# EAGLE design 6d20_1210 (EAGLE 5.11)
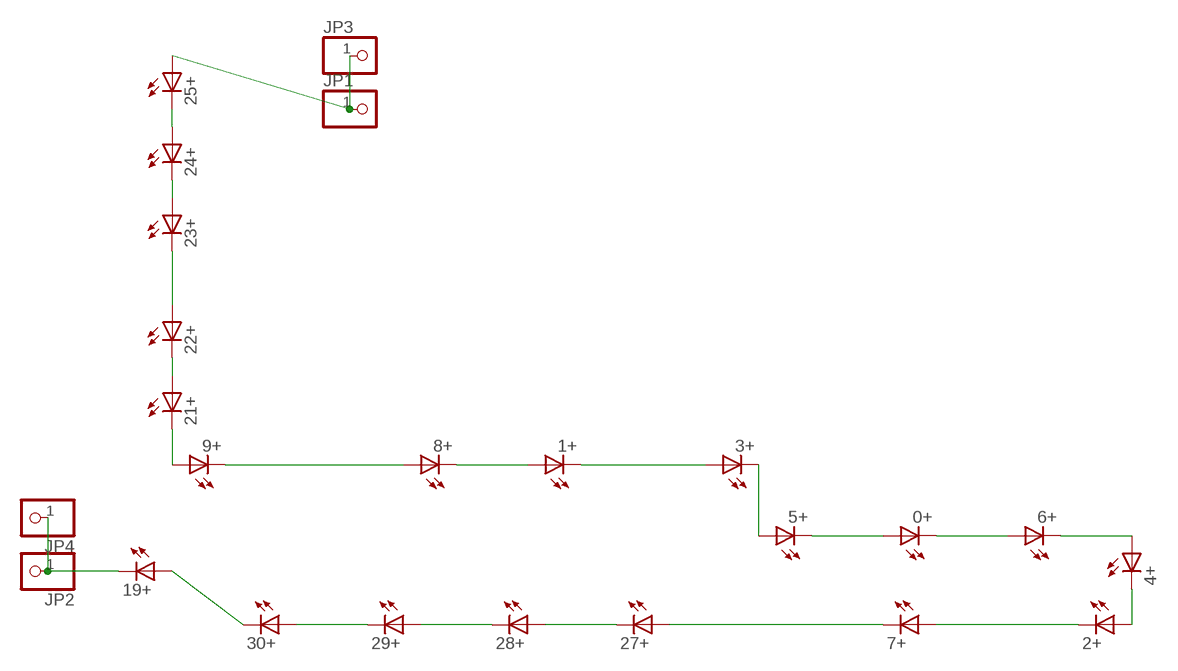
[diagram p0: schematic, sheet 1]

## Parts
0+  LED1210  [1210]
1+  LED1210  [1210]
2+  LED1210  [1210]
3+  LED1210  [1210]
4+  LED1210  [1210]
5+  LED1210  [1210]
6+  LED1210  [1210]
7+  LED1210  [1210]
8+  LED1210  [1210]
9+  LED1210  [1210]
19+  LED1210  [1210]
21+  LED1210  [1210]
22+  LED1210  [1210]
23+  LED1210  [1210]
24+  LED1210  [1210]
25+  LED1210  [1210]
27+  LED1210  [1210]
28+  LED1210  [1210]
29+  LED1210  [1210]
30+  LED1210  [1210]
JP1  PINHD-1X11MM6  [1X1MM8]
JP2  PINHD-1X11MM6  [1X1MM8]
JP3  PINHD-1X11X0.4  [1X01]
JP4  PINHD-1X11X0.4  [1X01]

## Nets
MINUS: 19+.P$2(C) JP2.1 JP4.1
N$4: 19+.P$1(A) 30+.P$2(C)
N$6: 8+.P$1(A) 9+.P$2(C)
N$7: 29+.P$2(C) 30+.P$1(A)
N$8: 28+.P$2(C) 29+.P$1(A)
N$9: 27+.P$2(C) 28+.P$1(A)
N$12: 2+.P$2(C) 7+.P$1(A)
N$13: 7+.P$2(C) 27+.P$1(A)
N$14: 2+.P$1(A) 4+.P$2(C)
N$15: 4+.P$1(A) 6+.P$2(C)
N$16: 0+.P$2(C) 6+.P$1(A)
N$17: 0+.P$1(A) 5+.P$2(C)
N$18: 3+.P$2(C) 5+.P$1(A)
N$19: 1+.P$2(C) 3+.P$1(A)
N$20: 1+.P$1(A) 8+.P$2(C)
N$23: 9+.P$1(A) 21+.P$2(C)
N$24: 21+.P$1(A) 22+.P$2(C)
N$25: 22+.P$1(A) 23+.P$2(C)
N$26: 24+.P$1(A) 25+.P$2(C)
N$28: 23+.P$1(A) 24+.P$2(C)
PLUS: 25+.P$1(A) JP1.1 JP3.1

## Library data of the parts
0+ 1+ 2+ 3+ 4+ 5+ 6+ 7+ 8+ 9+ 19+ 21+ 22+ 23+ 24+ 25+ 27+ 28+ 29+ 30+ = led(2):LED: LED
JP1-JP4 = pinhead:PINHD-1X1: PIN HEADER

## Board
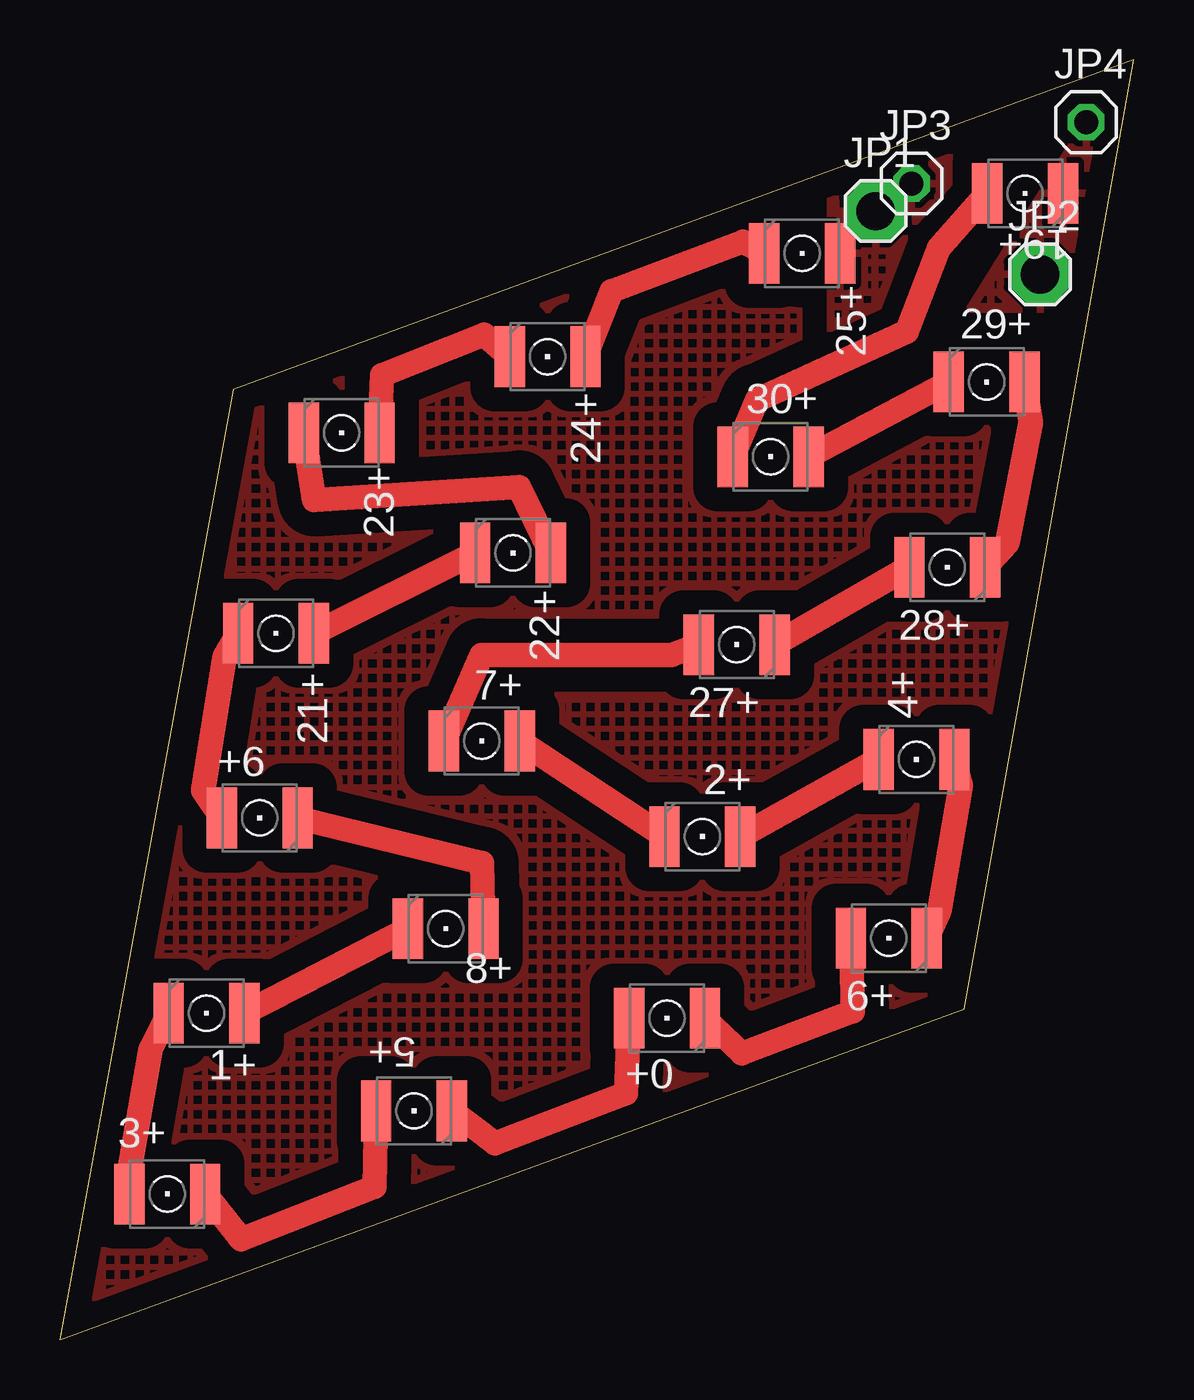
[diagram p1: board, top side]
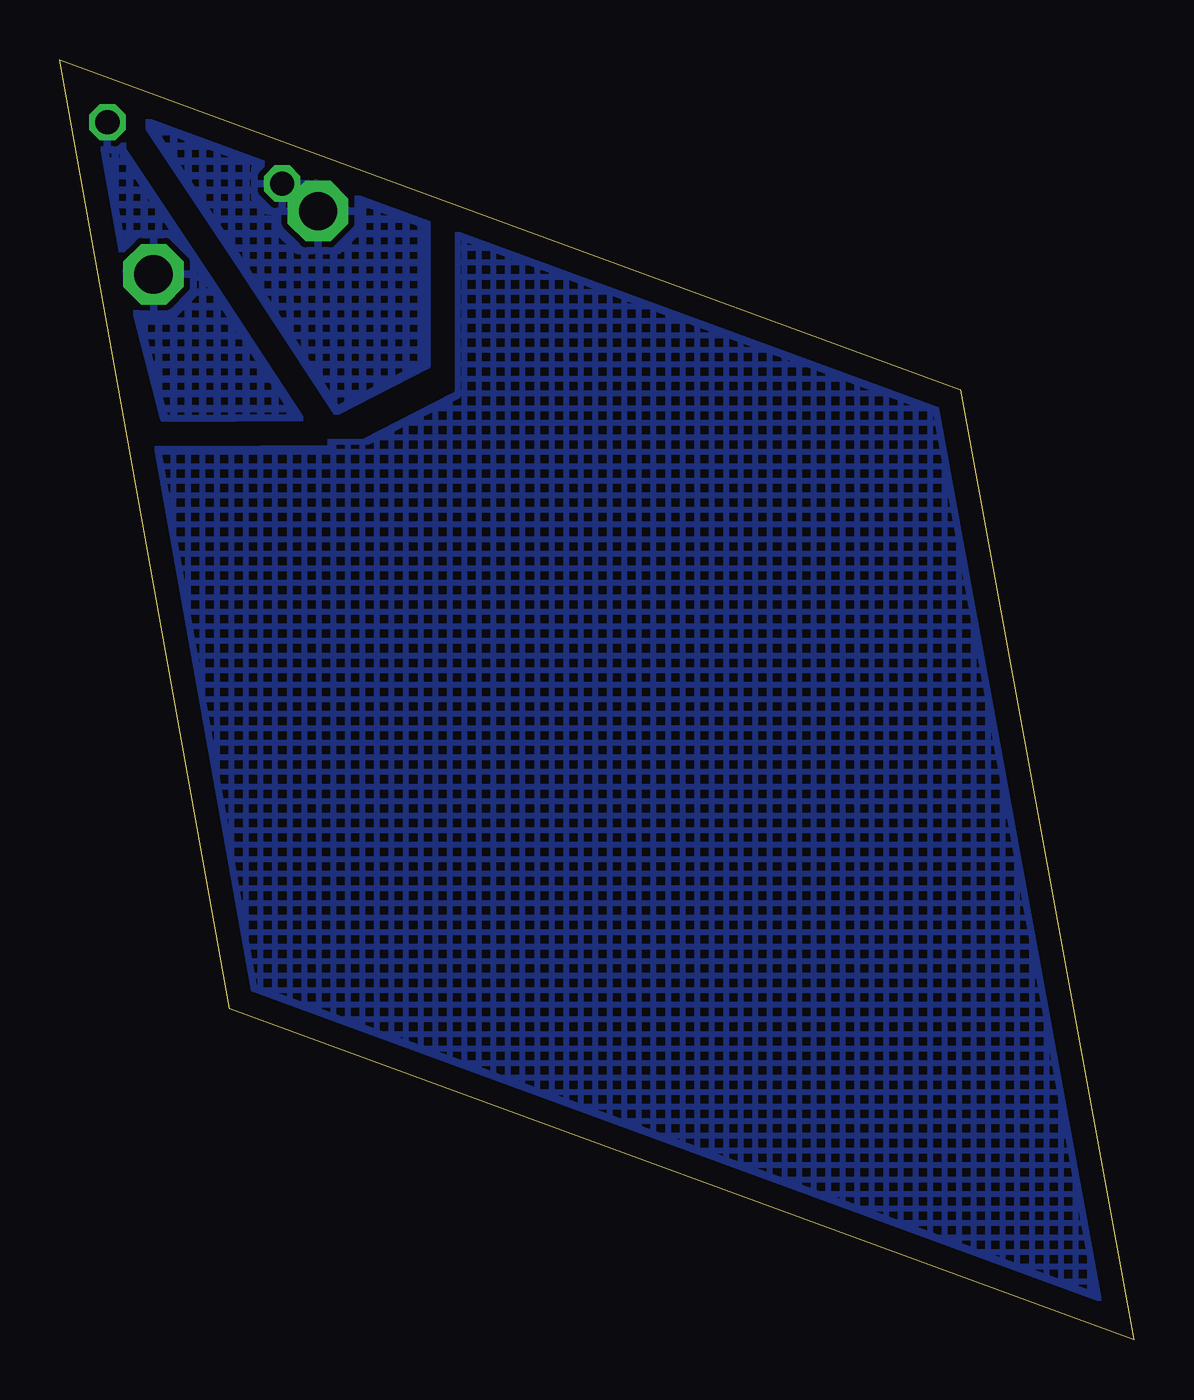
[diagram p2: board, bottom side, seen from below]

Size 45 x 53.62 mm. Coordinates in mm from the lower left corner, seen from the top.
Outline: 0,0 37.89,13.87 45,53.62 7.27,39.8 0,0
Copper layers (1*16): Top 0.035mm / dielectric 1.5mm / Bottom 0.035mm
Design rules "default": minimum track width 10mil, minimum drill 24mil, track to track 8mil, track to pad 8mil, pad to pad 8mil, via to via 8mil, smd to smd 8mil, copper to edge 40mil, drill to drill 8mil, minimum pad ring 10mil, minimum via ring 8mil, stop-mask expansion 4mil, vias tented up to drill 0mil, thermal gap 10mil

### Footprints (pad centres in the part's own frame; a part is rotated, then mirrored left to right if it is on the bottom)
1210 = smd 1.27 x 2.54: P$1 1.587,0; P$2 -1.587,0
1X1MM8 = drill 1.6 pad 2.54 octagon: 1 0,0
1X01 = drill 1.016 octagon: 1 0,0

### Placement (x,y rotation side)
0+  25.44,13.47 180 top
1+  6.15,13.68 0 top
2+  26.92,21.08 0 top
3+  4.51,6.11 180 top
4+  35.89,24.31 0 top
5+  14.84,9.59 180 top
6+  34.73,16.82 180 top
7+  17.68,25.08 0 top
8+  16.17,17.22 0 top
9+  8.38,21.86 180 top
19+  40.44,48.02 180 top
21+  9.06,29.59 0 top
22+  18.99,32.96 0 top
23+  11.81,37.99 0 top
24+  20.44,41.18 0 top
25+  31.1,45.51 0 top
27+  28.36,29.12 180 top
28+  37.18,32.36 180 top
29+  38.83,40.12 0 top
30+  29.78,36.99 0 top
JP1  34.18,47.28 0 top
JP2  41.07,44.63 0 top
JP3  35.68,48.43 0 top
JP4  43,51 0 top

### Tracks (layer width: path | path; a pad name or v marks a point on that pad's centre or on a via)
MINUS
  pour Top (isolate 0.813, rank 2, hatched): 44.45,53.34 38.1,43.18 43.18,43.18
  pour Bottom (isolate 0.813, rank 2, hatched): 44.45,53.34 34.58,38.63 40.64,38.58
N$1
  pour Top (isolate 1.016, rank 3, hatched): 0,0 38.1,13.97 41.91,41.91 30.48,43.18 29.21,46.99 8,39
  pour Bottom (isolate 1.016, rank 3, hatched): 6.35,39.37 0,0 38.1,13.97 41.91,41.91 30.48,43.18 29.21,46.99
N$4
  Top 1.016: 30+.P$2 29.21,39.37 35.48,42.23 36.83,45.72 19+.P$1
N$6
  Top 1.016: 8+.P$1 17.7,19.97 9+.P$2
N$7
  Top 1.016: 30+.P$1 29+.P$2
N$8
  Top 1.016: 28+.P$2 39.69,33.37 40.68,38.45 29+.P$1
N$9
  Top 1.016: 27+.P$2 28+.P$1
N$12
  Top 1.016: 7+.P$1 2+.P$2
N$13
  Top 1.016: 7+.P$2 17.67,28.69 25.63,28.68 27+.P$1
N$14
  Top 1.016: 2+.P$1 4+.P$2
N$15
  Top 1.016: 6+.P$2 36.85,17.97 37.74,23.25 4+.P$1
N$16
  Top 1.016: 0+.P$2 28.57,12 33.22,13.76 6+.P$1
N$17
  Top 1.016: 5+.P$2 18.23,8.22 23.73,10.33 0+.P$1
N$18
  Top 1.016: 3+.P$2 7.61,4.22 13.19,6.41 5+.P$1
N$19
  Top 1.016: 3+.P$1 2.96,7.28 3.81,12.19 1+.P$2
N$20
  Top 1.016: 1+.P$1 8+.P$2
N$23
  Top 1.016: 9+.P$1 6,23 6.91,28.62 21+.P$2
N$24
  Top 1.016: 21+.P$1 22+.P$2
N$25
  Top 1.016: 22+.P$1 19.25,35.72 10.66,35.18 23+.P$2
N$26
  Top 1.016: 24+.P$1 23.11,43.92 28.63,46 25+.P$2
N$28
  Top 1.016: 23+.P$1 13.5,40.41 17.77,42.1 24+.P$2
PLUS
  pour Top (isolate 0.813, hatched): 39.37,50.8 36.83,46.99 35.56,42.29 32.29,42.29 32.29,48.64
  pour Bottom (isolate 0.813, hatched): 42.27,52.28 37.5,45.11 33.41,38.85 29.6,40.81 29.6,47.16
